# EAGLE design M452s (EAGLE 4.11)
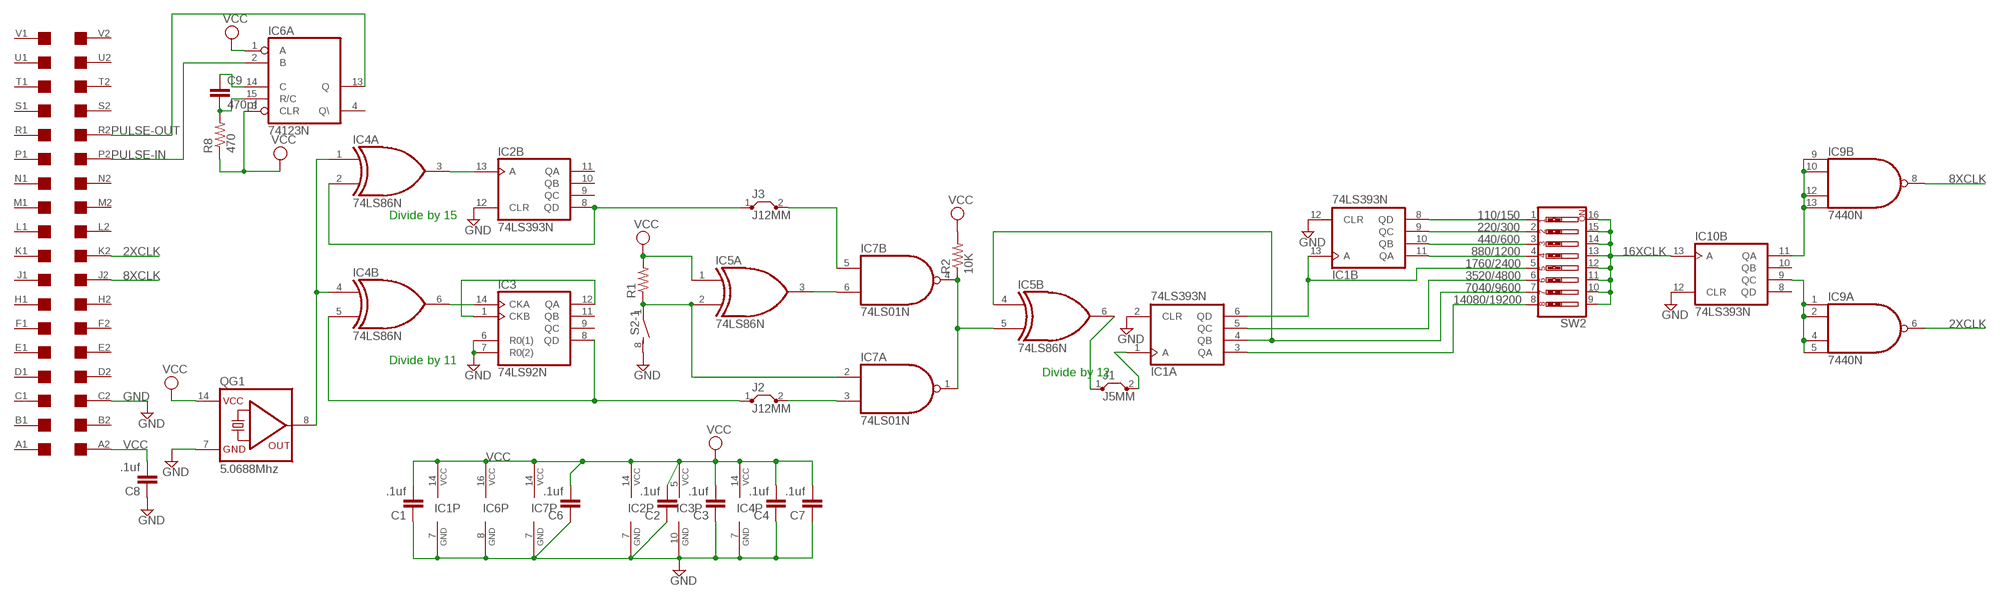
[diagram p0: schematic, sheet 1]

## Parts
C1  .1uf  C-EU050-025X075  [C050-025X075]
C2  .1uf  C-EU050-025X075  [C050-025X075]
C3  .1uf  C-EU050-025X075  [C050-025X075]
C4  .1uf  C-EU050-025X075  [C050-025X075]
C6  .1uf  C-EU050-025X075  [C050-025X075]
C7  .1uf  C-EU050-025X075  [C050-025X075]
C8  .1uf  C-EU050-025X075  [C050-025X075]
C9  470pf  C-EU050-025X075  [C050-025X075]
IC1  74LS393N  [DIL14]
IC2  74LS393N  [DIL14]
IC3  74LS92N  [DIL14]
IC4  74LS86N  [DIL14]
IC5  74LS86N  [DIL14]
IC6  74123N  [DIL16]
IC7  74LS01N  [DIL14]
IC9  7440N  74S20N  [DIL14]
IC10  74LS393N  [DIL14]
J1  J5MM  [05]
J2  J12MM  [12]
J3  J12MM  [12]
QG1  5.0688Mhz  QG5860  [DIL14S]
R1  R-US_0204/7  [0204/7]
R2  10K  R-US_0204/7  [0204/7]
R8  470  R-US_0204/7  [0204/7]
S2  DIP04S  [DIP04S]
SW2  SW_DIP-8  [EDG-08]
U$1  DEC-FLIPCHIP  [DEC-FLIPCHIP]

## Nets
2XCLK: IC9.6(A:O) U$1.K2
8XCLK: IC9.8(B:O) U$1.J2
16XCLK: IC10.13(B:A) SW2.9 SW2.10 SW2.11 SW2.12 SW2.13 SW2.14 SW2.15 SW2.16
110/150: IC1.8(B:QD) SW2.1
220/300: IC1.9(B:QC) SW2.2
440/600: IC1.10(B:QB) SW2.3
880/1200: IC1.11(B:QA) SW2.4
1760/2400: IC1.6(A:QD) IC1.13(B:A) SW2.5
3520/4800: IC1.5(A:QC) SW2.6
7040/9600: IC1.4(A:QB) IC5.4(B:I0) SW2.7
14080/19200: IC1.3(A:QA) SW2.8
GND: C1.1 C2.1 C3.1 C4.1 C6.1 C7.1 C8.1 IC1.2(A:CLR) IC1.7(P:GND) IC1.12(B:CLR) IC2.7(P:GND) IC2.12(B:CLR) IC3.6(R0(1)) IC3.7(R0(2)) IC3.10(GND) IC4.7(P:GND) IC6.8(P:GND) IC7.7(P:GND) IC10.12(B:CLR) QG1.7(GND) S2.8 U$1.C2
N$1: IC4.1(A:I0) IC4.4(B:I0) QG1.8(OUT)
N$2: IC2.8(B:QD) IC4.2(A:I1) J3.1
N$3: IC3.8(QD) IC4.5(B:I1) J2.1
N$4: IC3.1(CKB) IC3.12(QA)
N$5: IC3.14(CKA) IC4.6(B:O)
N$6: IC2.13(B:A) IC4.3(A:O)
N$7: IC5.6(B:O) J1.1
N$8: IC5.2(A:I1) IC7.2(A:I0) R1.1 S2.1
N$9: IC5.5(B:I1) IC7.1(A:O) IC7.4(B:O) R2.1
N$10: IC9.1(A:I0) IC9.2(A:I1) IC9.4(A:I2) IC9.5(A:I3) IC10.9(B:QC)
N$11: IC1.1(A:A) J1.2
N$12: IC9.9(B:I0) IC9.10(B:I1) IC9.12(B:I2) IC9.13(B:I3) IC10.11(B:QA)
N$13: IC7.5(B:I0) J3.2
N$14: IC7.3(A:I1) J2.2
N$15: IC5.3(A:O) IC7.6(B:I1)
N$21: C9.2 IC6.15(A:R/C) R8.2
N$22: C9.1 IC6.14(A:C)
PULSE-IN: IC6.2(A:B) U$1.P2
PULSE-OUT: IC6.13(A:Q) U$1.R2
VCC: C1.2 C2.2 C3.2 C4.2 C6.2 C7.2 C8.2 IC1.14(P:VCC) IC2.14(P:VCC) IC3.5(VCC) IC4.14(P:VCC) IC5.1(A:I0) IC6.1(A:A) IC6.3(A:CLR) IC6.16(P:VCC) IC7.14(P:VCC) QG1.14(VCC) R1.2 R2.2 R8.1 U$1.A2
Unconnected: IC2.1(A:A) IC2.2(A:CLR) IC2.3(A:QA) IC2.4(A:QB) IC2.5(A:QC) IC2.6(A:QD) IC2.9(B:QC) IC2.10(B:QB) IC2.11(B:QA) IC3.9(QC) IC3.11(QB) IC4.8(C:O) IC4.9(C:I0) IC4.10(C:I1) IC4.11(D:O) IC4.12(D:I0) IC4.13(D:I1) IC5.8(C:O) IC5.9(C:I0) IC5.10(C:I1) IC5.11(D:O) IC5.12(D:I0) IC5.13(D:I1) IC6.4(A:Q\) IC6.5(B:Q) IC6.6(B:C) IC6.7(B:R/C) IC6.9(B:A) IC6.10(B:B) IC6.11(B:CLR) IC6.12(B:Q\) IC7.8(C:I0) IC7.9(C:I1) IC7.10(C:O) IC7.11(D:I0) IC7.12(D:I1) IC7.13(D:O) IC10.1(A:A) IC10.2(A:CLR) IC10.3(A:QA) IC10.4(A:QB) IC10.5(A:QC) IC10.6(A:QD) IC10.8(B:QD) IC10.10(B:QB) S2.2 S2.3 S2.4 S2.5 S2.6 S2.7 U$1.A1 U$1.B1 U$1.B2 U$1.C1 U$1.D1 U$1.D2 U$1.E1 U$1.E2 U$1.F1 U$1.F2 U$1.H1 U$1.H2 U$1.J1 U$1.K1 U$1.L1 U$1.L2 U$1.M1 U$1.M2 U$1.N1 U$1.N2 U$1.P1 U$1.R1 U$1.S1 U$1.S2 U$1.T1 U$1.T2 U$1.U1 U$1.U2 U$1.V1 U$1.V2

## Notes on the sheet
- Divide by 15
- Divide by 11
- Divide by 12

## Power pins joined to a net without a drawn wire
GND: IC5.7(P:GND) IC9.7(P:GND) IC10.7(P:GND)
VCC: IC5.14(P:VCC) IC9.14(P:VCC) IC10.14(P:VCC)

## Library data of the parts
C1-C4 C6-C9 = rcl:C-EU: CAPACITOR, European symbol
IC1 IC2 IC10 = 74xx-us:74*393: Dual 4-bit decade and binary COUNTER
IC3 = 74xx-us:74*92: Decade, divide by twelve and binary COUNTER
IC4 IC5 = 74xx-us:74*86: Quad 2-input EXCLUSIV-OR (XOR) gate
IC6 = 74xx-us:74*123: Retriggerable monostable MULTIVIBRATOR
IC7 = 74xx-us:74*01: Quad 2-input NAND gate, open collector
IC9 = 74xx-us:74*20: Dual 4-input NAND gate
J1-J3 = jumper:J: Bridge
QG1 = crystal:QG5860: CRYSTAL RESONATOR
R1 R2 R8 = rcl:R-US_: RESISTOR, American symbol
S2 = switch-dil:DIP04S: DIL/CODE SWITCH
SW2 = special:SW_DIP-8: DIP SWITCH
U$1 = con-dec:DEC-FLIPCHIP: DEC Flip-Chip single card fingers

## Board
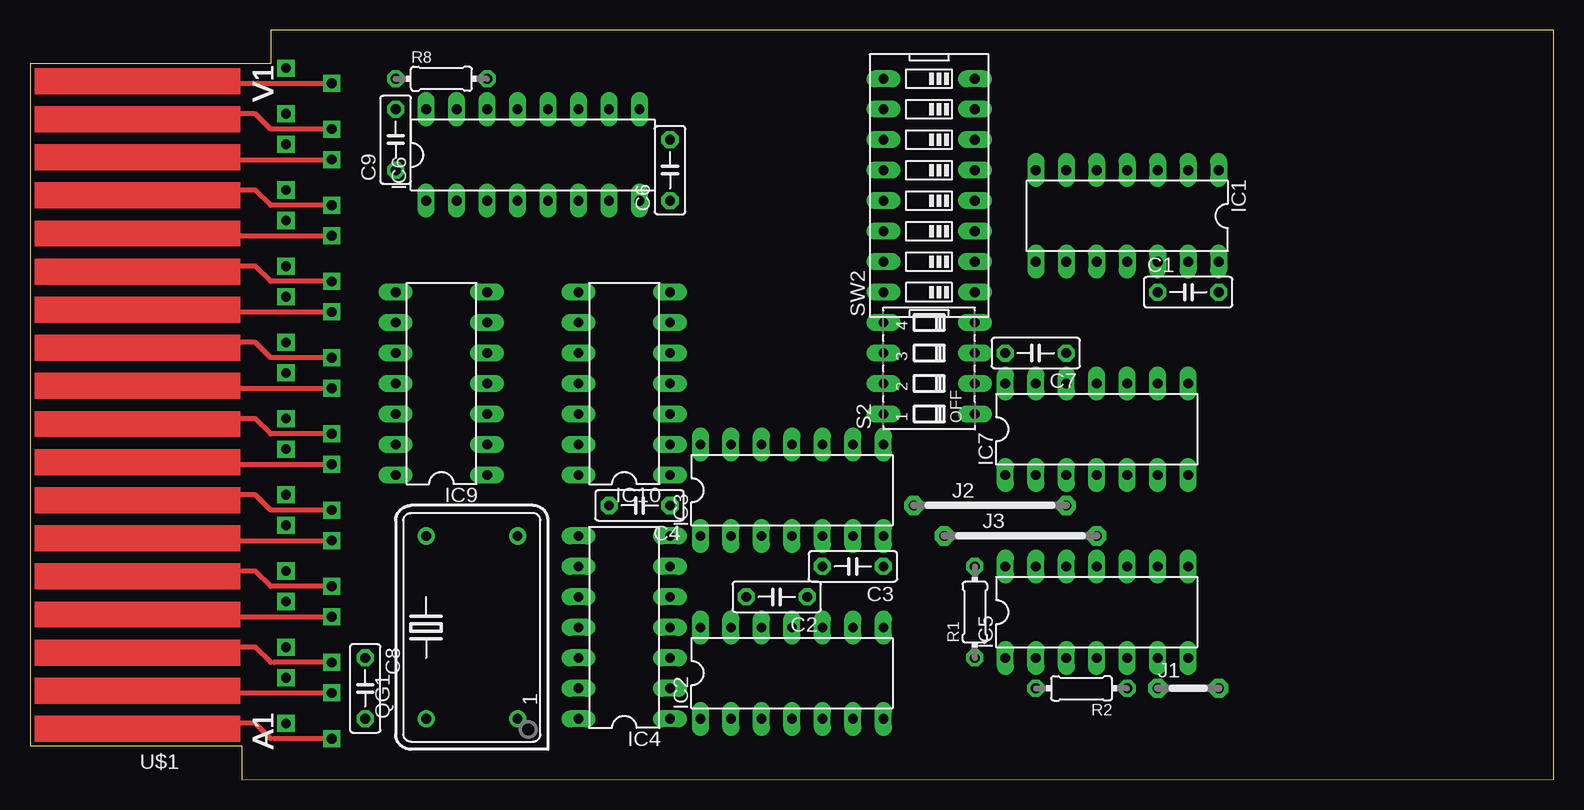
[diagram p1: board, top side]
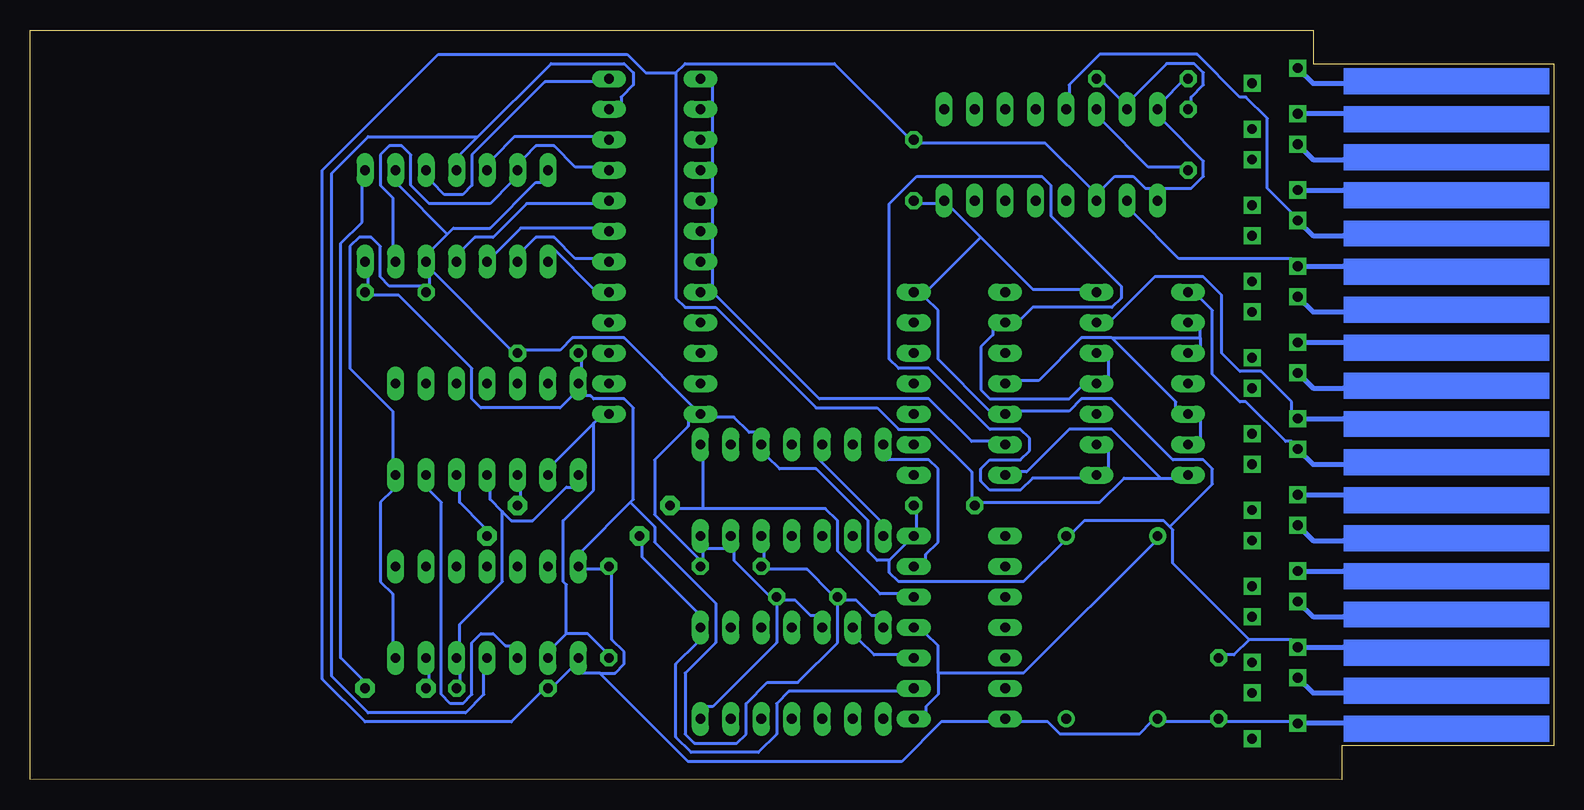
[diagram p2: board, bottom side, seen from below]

Size 126.98 x 62.48 mm. Coordinates in mm from the lower left corner, seen from the top.
Outline: 0,2.83 17.65,2.83 17.65,0 126.98,0.04 126.98,62.45 20.06,62.48 20.06,59.65 0,59.65 0,2.83
Copper layers (1*16): Top 0.035mm / dielectric 1.5mm / Bottom 0.035mm
Design rules "10mils": minimum track width 10mil, minimum drill 28mil, track to track 15mil, track to pad 10mil, pad to pad 10mil, via to via 10mil, smd to smd 10mil, copper to edge 40mil, drill to drill 10mil, minimum pad ring 12mil, minimum via ring 8mil, stop-mask expansion 0mil, vias tented up to drill 0mil, thermal gap 10mil

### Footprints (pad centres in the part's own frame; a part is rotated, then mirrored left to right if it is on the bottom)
C050-025X075 = drill 0.813 octagon: 1 -2.54,0; 2 2.54,0
DIL14 = drill 0.813 long: 1 -7.62,-3.81; 2 -5.08,-3.81; 3 -2.54,-3.81; 4 0,-3.81; 5 2.54,-3.81; 6 5.08,-3.81; 7 7.62,-3.81; 8 7.62,3.81; 9 5.08,3.81; 10 2.54,3.81; 11 0,3.81; 12 -2.54,3.81; 13 -5.08,3.81; 14 -7.62,3.81
DIL16 = drill 0.813 long: 1 -8.89,-3.81; 2 -6.35,-3.81; 3 -3.81,-3.81; 4 -1.27,-3.81; 5 1.27,-3.81; 6 3.81,-3.81; 7 6.35,-3.81; 8 8.89,-3.81; 9 8.89,3.81; 10 6.35,3.81; 11 3.81,3.81; 12 1.27,3.81; 13 -1.27,3.81; 14 -3.81,3.81; 15 -6.35,3.81; 16 -8.89,3.81
05 = drill 0.813 pad 1.6 octagon: 1 -2.54,0; 2 2.54,0
12 = drill 0.813 pad 1.6 octagon: 1 -6.35,0; 2 6.35,0
DIL14S = drill 0.813 round: 1 -7.62,-3.81; 7 7.62,-3.81; 8 7.62,3.81; 14 -7.62,3.81
0204/7 = drill 0.813 octagon: 1 -3.81,0; 2 3.81,0
DIP04S = drill 0.813 long: 1 -3.81,-3.81; 2 -1.27,-3.81; 3 1.27,-3.81; 4 3.81,-3.81; 5 3.81,3.81; 6 1.27,3.81; 7 -1.27,3.81; 8 -3.81,3.81
EDG-08 = drill 0.813 long: 1 -8.89,-3.81; 2 -6.35,-3.81; 3 -3.81,-3.81; 4 -1.27,-3.81; 5 1.27,-3.81; 6 3.81,-3.81; 7 6.35,-3.81; 8 8.89,-3.81; 9 8.89,3.81; 10 6.35,3.81; 11 3.81,3.81; 12 1.27,3.81; 13 -1.27,3.81; 14 -3.81,3.81; 15 -6.35,3.81; 16 -8.89,3.81
DEC-FLIPCHIP = drill 0.813 square: A1 -7.62,27.94; A2 -3.81,26.67; B1 -7.62,24.13; B2 -3.81,22.86; C1 -7.62,21.59; C2 -3.81,20.32; D1 -7.62,17.78; D2 -3.81,16.51; E1 -7.62,15.24; E2 -3.81,13.97; F1 -7.62,11.43; F2 -3.81,10.16; H1 -7.62,8.89; H2 -3.81,7.62; J1 -7.62,5.08; J2 -3.81,3.81; K1 -7.62,2.54; K2 -3.81,1.27; L1 -7.62,-1.27; L2 -3.81,-2.54; M1 -7.62,-3.81; M2 -3.81,-5.08; N1 -7.62,-7.62; N2 -3.81,-8.89; P1 -7.62,-10.16; P2 -3.81,-11.43; R1 -7.62,-13.97; R2 -3.81,-15.24; S1 -7.62,-16.51; S2 -3.81,-17.78; T1 -7.62,-20.32; T2 -3.81,-21.59; U1 -7.62,-22.86; U2 -3.81,-24.13; V1 -7.62,-26.67; V2 -3.81,-27.94

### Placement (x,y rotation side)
C1  96.52,40.64 0 top
C2  62.22,15.24 180 top
C3  68.58,17.78 180 top
C4  50.79,22.86 180 top
C6  53.34,50.8 90 top
C7  83.81,35.56 180 top
C8  27.94,7.62 270 top
C9  30.48,53.34 90 top
IC1  91.44,46.99 180 top
IC2  63.49,8.89 0 top
IC3  63.49,24.13 0 top
IC4  49.52,12.7 90 top
IC5  88.9,13.97 0 top
IC6  41.9,52.07 0 top
IC7  88.9,29.21 0 top
IC9  34.28,33.02 90 top
IC10  49.52,33.02 90 top
J1  96.52,7.62 0 top
J2  80.01,22.86 0 top
J3  82.55,20.32 0 top
QG1  36.82,12.7 90 top
R1  78.73,13.97 90 top
R2  87.62,7.62 180 top
R8  34.28,58.42 0 top
S2  74.93,34.29 90 top
SW2  74.93,49.53 90 top
U$1  17.52,31.37 180 top

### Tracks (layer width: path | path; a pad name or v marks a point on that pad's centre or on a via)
2XCLK
  Bottom 0.254: U$1.K2 21.84,30.73 21.84,31.5 24.38,34.04 26.16,34.04 27.68,35.56 27.68,40.39 29.21,41.91 33.27,41.91 36.82,38.35 IC9.6
8XCLK
  Bottom 0.254: U$1.J2 21.84,28.19 22.35,28.19 25.65,31.5 26.16,31.5 28.44,33.78 28.44,39.12 29.46,40.13 IC9.8
16XCLK
  Bottom 0.254: IC10.13 46.98,28.19 48.51,28.19 52.06,31.75 61.21,31.75 69.84,40.39 SW2.16 70.1,41.15 70.1,42.67 SW2.15 70.1,43.69 70.1,45.21 SW2.14 70.1,46.23 70.1,47.75 SW2.13 70.1,48.77 70.1,50.29 SW2.12 70.1,51.31 70.1,52.83 SW2.11 70.1,53.85 70.1,55.37 SW2.10 70.1,56.39 70.1,57.91 SW2.9
110/150
  Bottom 0.254: SW2.1 80.01,40.89 83.31,44.2 IC1.8
220/300
  Bottom 0.254: SW2.2 80.01,43.43 81.53,43.43 83.31,45.21 84.83,45.21 85.85,44.2 IC1.9
440/600
  Bottom 0.254: SW2.3 80.01,45.97 86.1,45.97 IC1.10
880/1200
  Bottom 0.254: SW2.4 80.01,48.01 85.59,48.01 88.39,45.21 89.91,45.21 90.93,44.2 IC1.11
1760/2400
  Bottom 0.254: SW2.5 80.01,51.05 81.53,51.05 83.31,52.83 84.83,52.83 85.85,51.82 IC1.6 86.86,49.78 88.64,48.01 93.72,48.01 95.25,49.53 95.25,52.07 96.01,52.83 97.02,52.83 97.79,52.07 97.79,49.53 96.77,48.51 96.77,44.45 IC1.13
3520/4800
  Bottom 0.254: SW2.6 80.01,53.59 86.61,53.59 88.39,51.82 IC1.5
7040/9600
  Bottom 0.254: 89.66,53.59 83.56,59.69 77.47,59.69 76.7,58.93 76.7,57.91 77.72,56.9 77.72,56.39 SW2.7 | 89.66,53.59 91.18,52.07 IC1.4 | 89.66,53.59 98.8,53.59 101.85,50.55 101.85,8.64 98.8,5.59 90.67,5.59 89.15,7.11 89.15,8.89 IC5.4
14080/19200
  Bottom 0.254: SW2.8 80.01,58.17 84.07,58.17 90.17,52.07 90.17,49.53 90.93,48.77 92.45,48.77 93.47,49.78 IC1.3
GND
  Bottom 0.254: 47.75,45.21 43.43,40.89 39.36,40.89 IC9.7 | 47.75,45.21 IC6.8 51.3,48.01 52.83,48.01 C6.1 | 47.75,45.21 52.06,40.89 IC10.7 52.32,40.13 51.3,39.12 51.3,35.05 46.98,30.73 IC10.12 44.45,30.73 40.38,30.73 39.36,31.75 36.82,31.75 31.75,26.67 29.21,26.67 28.44,25.91 28.44,24.64 32,21.08 | 25.39,11.68 26.67,10.41 27.43,10.41 C8.1 | 25.39,11.68 21.84,11.68 U$1.C2 | 55.37,18.29 55.37,17.27 54.6,16.51 44.19,16.51 40.89,19.81 QG1.7 40.13,20.57 39.11,21.59 32.51,21.59 32,21.08 | 55.37,18.29 IC4.7 53.08,20.83 53.08,22.35 C4.1 | 25.39,11.68 31.75,18.03 31.75,20.83 32,21.08 | S2.8 69.84,30.23 68.32,30.23 67.05,28.96 66.54,28.96 IC3.10 65.53,26.92 64.51,25.91 61.46,25.91 57.14,21.59 57.14,19.05 56.38,18.29 55.37,18.29 | IC2.12 61.46,13.72 61.97,13.72 63.24,14.99 64.26,14.99 C2.1 | IC2.7 70.61,6.1 70.1,6.1 64.77,11.43 C2.1 | C2.1 65.27,15.24 68.32,18.29 68.32,19.05 IC3.6 69.08,19.3 70.61,19.3 IC3.7 70.86,19.05 70.86,18.29 C3.1 71.12,18.29 74.93,22.1 74.93,26.67 72.13,29.46 72.13,29.97 S2.8 | IC5.7 96.77,11.43 96.77,15.49 97.79,16.51 97.79,23.11 96.77,24.13 IC7.7 96.77,26.67 96.77,30.73 100.33,34.29 100.33,44.45 99.56,45.21 98.55,45.21 97.79,44.45 97.79,41.91 97.02,41.15 94.23,41.15 C1.1 93.72,41.15 93.72,41.91 IC1.12 | 92.2,45.47 93.47,44.2 IC1.12 | 92.2,45.47 91.69,45.97 88.64,45.97 84.83,49.78 84.32,49.78 IC1.7 | 92.2,45.47 96.26,49.53 IC1.2 | IC1.12 93.47,42.42 86.86,35.81 C7.1 85.85,35.81 82.8,35.81 81.78,36.83 77.47,36.83 S2.8
N$1
  Bottom 0.254: 51.3,8.89 51.3,11.18 52.32,12.19 IC4.4 | 51.3,8.89 51.3,7.11 52.32,6.1 52.32,5.59 IC4.1 | 51.3,8.89 44.19,8.89 33.27,19.81 QG1.8
N$2
  Bottom 0.254: IC4.2 54.6,7.37 63.75,7.37 64.77,6.35 64.77,3.81 66.29,2.29 71.88,2.29 73.15,3.56 73.15,9.65 71.37,11.43 IC2.8 71.37,13.97 75.94,18.54 75.94,19.56 J3.1
N$3
  Bottom 0.254: 70.86,22.61 72.89,22.61 J2.1 | 70.86,22.61 60.7,22.61 59.68,21.59 59.68,19.05 56.13,15.49 54.6,15.49 IC4.5 | 70.86,22.61 70.86,26.67 IC3.8
N$4
  Bottom 0.254: IC3.1 56.13,21.59 61.21,26.67 IC3.12
N$5
  Bottom 0.254: IC4.6 52.32,18.29 52.32,18.8 51.3,19.81 51.3,25.91 52.06,26.67 55.62,26.67 IC3.14
N$6
  Bottom 0.254: IC4.3 54.6,10.41 56.64,10.41 57.91,11.68 IC2.13
N$7
  Bottom 0.254: IC5.6 93.72,8.89 93.72,8.38 J1.1
N$8
  Bottom 0.254: 82.29,12.19 80.51,12.19 78.99,10.67 R1.1 | 82.29,12.19 83.31,11.18 IC5.2 | 80.01,29.72 83.31,26.42 IC7.2 | 80.01,29.72 79.75,29.97 S2.1 | 82.29,12.19 82.29,16.26 82.55,16.51 82.55,21.59 80.01,24.13 80.01,29.72
N$9
  Bottom 0.254: R2.1 91.18,8.13 91.18,8.89 IC5.5 91.18,11.43 91.18,12.95 87.62,16.51 87.62,22.35 | 87.62,22.35 88.64,23.37 88.64,24.13 IC7.4 | 87.62,22.35 86.86,21.59 85.09,21.59 82.29,24.38 81.78,24.38 IC7.1
N$10
  Bottom 0.254: IC9.2 37.08,27.43 37.08,25.91 IC9.1 39.36,25.15 43.43,25.15 44.45,24.13 46.98,24.13 47.75,24.89 47.75,25.91 46.98,26.67 44.45,26.67 43.68,27.43 43.68,28.45 44.45,29.21 46.98,29.21 52.06,34.29 54.6,34.29 55.37,35.05 55.37,48.01 53.08,50.29 42.67,50.29 41.9,49.53 41.9,46.99 36.06,41.15 36.06,40.13 36.82,39.37 43.43,39.37 44.45,38.35 IC10.9 46.73,37.59 46.73,37.08 47.75,36.07 47.75,32.51 46.98,31.75 40.38,31.75 39.36,32.77 IC9.4 37.08,33.53 37.08,35.05 IC9.5
N$11
  Bottom 0.254: IC1.1 99.31,49.53 99.31,46.48 101.09,44.7 101.09,10.16 99.31,8.38 J1.2
N$12
  Bottom 0.254: IC9.13 29.46,28.45 29.46,29.97 IC9.12 31.49,30.99 31.49,31.5 36.82,36.83 | 29.46,36.83 29.46,37.59 IC9.9 | 29.46,36.83 29.46,36.07 IC9.10 | 36.82,36.83 29.46,36.83 | 36.82,36.83 39.36,36.83 42.92,33.27 44.45,33.27 IC10.11
N$13
  Bottom 0.254: IC7.5 91.18,24.13 91.18,23.11 89.15,21.08 J3.2
N$14
  Bottom 0.254: IC7.3 86.1,24.13 86.1,23.62 J2.2
N$15
  Bottom 0.254: IC5.3 86.86,11.18 87.37,11.18 88.39,12.19 89.4,12.19 90.17,11.43 90.17,7.11 90.93,6.35 91.94,6.35 92.7,7.11 92.7,23.11 93.72,24.13 IC7.6
N$21
  Bottom 0.254: C9.2 30.22,56.39 30.22,56.9 29.21,57.91 29.21,58.93 29.97,59.69 32.25,59.69 35.05,56.9 IC6.15 36.06,56.64 37.59,58.17 R8.2
N$22
  Bottom 0.254: C9.1 30.98,51.05 33.78,51.05 37.59,54.86 IC6.14
PULSE-IN
  Bottom 0.254: U$1.P2 21.84,43.43 31.24,43.43 35.05,47.24 IC6.2
PULSE-OUT
  Bottom 0.254: U$1.R2 21.84,47.24 23.87,49.28 23.87,55.12 25.65,56.9 26.16,56.9 29.71,60.45 37.84,60.45 40.38,57.91 40.38,57.15 IC6.13
VCC
  Bottom 0.254: 32.76,25.15 35.81,25.15 37.84,23.11 47.75,23.11 C4.2 48.51,23.37 48.51,25.65 52.06,29.21 54.6,29.21 56.38,30.99 61.46,30.99 69.84,39.37 72.39,39.37 73.15,40.13 73.15,58.93 | 32.76,25.15 31.75,25.15 IC9.14 | 32.76,25.15 36.82,29.21 40.38,29.21 43.94,25.65 44.45,25.65 IC10.14 | R8.1 30.98,58.17 32.51,56.64 IC6.16 32.51,54.86 29.21,51.56 29.21,50.29 30.22,49.28 32.51,49.28 IC6.1 33.52,49.28 34.03,49.28 35.05,50.29 36.57,50.29 37.59,49.28 IC6.3 38.6,49.28 42.41,53.09 52.83,53.09 C6.2 53.84,53.59 59.94,59.69 72.39,59.69 73.15,58.93 | U$1.A2 21.84,4.83 27.43,4.83 C8.2 28.44,4.83 32.51,4.83 QG1.14 33.52,4.83 34.54,3.81 41.14,3.81 42.16,4.83 44.45,4.83 IC4.14 46.98,4.83 51.05,4.83 54.35,1.52 72.13,1.52 79.5,8.89 | IC3.5 65.78,19.05 65.78,18.29 C3.2 65.53,17.53 62.22,17.53 60.19,15.49 C2.2 | IC2.14 56.38,13.72 56.89,13.72 58.16,14.99 59.18,14.99 C2.2 | IC1.14 98.8,41.91 98.8,41.15 C1.2 98.55,40.39 96.26,40.39 90.17,34.29 90.17,31.75 89.4,30.99 82.8,30.99 81.78,32 IC7.14 | IC7.14 81.02,34.29 81.02,35.05 C7.2 | 79.5,8.89 81.02,8.89 IC5.1 81.78,9.4 83.31,7.87 R2.2 84.32,7.37 86.86,4.83 99.06,4.83 102.61,8.38 102.61,50.8 92.96,60.45 77.21,60.45 75.69,58.93 73.15,58.93 | 79.5,8.89 78.23,8.89 77.47,9.65 77.47,10.67 78.48,11.68 78.48,17.27 R1.2 79.24,17.53 80.77,17.53 IC5.14 81.02,19.05 76.96,23.11 | 76.96,23.11 76.7,23.37 76.7,30.99 77.47,31.75 80.01,31.75 80.26,32 80.77,32 IC7.14 | 76.96,23.11 74.93,21.08 74.93,19.81 69.84,14.73 69.84,11.43 72.39,8.89 72.39,3.81 71.62,3.05 68.07,3.05 67.31,3.81 67.31,6.35 65.53,8.13 62.99,8.13 59.68,11.43 C2.2

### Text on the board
tNames: V1 | V1 | V1 | V1 | V1 | V1 | V1 | V1 | V1 | V1 | V1 | V1 | V1 | V1 | V1 | V1 | V1 | V1 | V1 | V1 | V1 | V1 | V1 | V1 | V1 | V1 | V1 | V1 | V1 | V1 | V1 | V1 | A1 | A1 | A1 | A1 | A1 | A1 | A1 | A1 | A1 | A1 | A1 | A1 | A1 | A1 | A1 | A1 | A1 | A1 | A1 | A1 | A1 | A1 | A1 | A1 | A1 | A1 | A1 | A1 | A1 | A1 | A1 | A1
